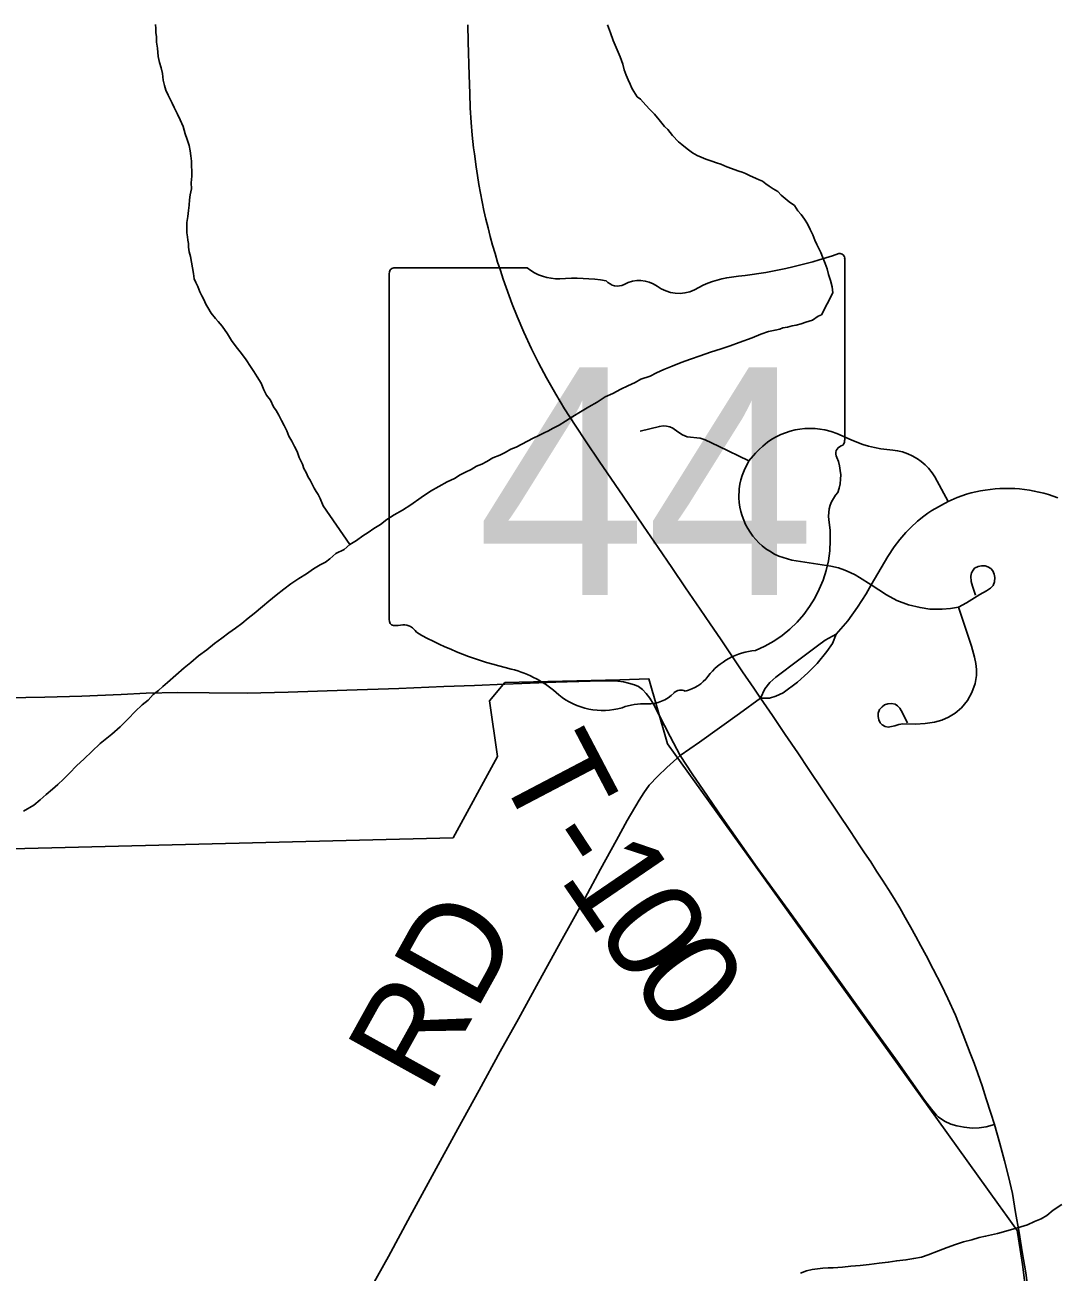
# Model space of a CAD drawing. Extents: x 103424 to 286016, y 38711 to 110967.
# Drawn here: x 143819 to 146990, y 92537 to 96372 of the extents above; entities that cross this region are included whole.
import ezdxf

# ---------------------------------------------------------------- set-up
doc = ezdxf.new("R2010")
doc.units = 0
for name, color, linetype in [('GM_X_City_Street', 7, 'Continuous'), ('GM_X_Corporation', 7, 'Continuous'), ('GM_X_County_Road', 7, 'Continuous'), ('GM_X_County_Road_Text', 7, 'Continuous'), ('GM_X_Major_River', 7, 'Continuous'), ('GM_X_Minor_River', 7, 'Continuous'), ('GM_X_State_Location', 7, 'Continuous'), ('GM_X_State_Route', 7, 'Continuous'), ('GM_X_State_Shield', 7, 'Continuous'), ('GM_X_Township_Road', 7, 'Continuous'), ('GM_X_Township_Road_Text', 7, 'Continuous')]:
    doc.layers.add(name, color=color, linetype=linetype)

msp = doc.modelspace()

# ---------------------------------------------------------------- linework, layer by layer
at = {"layer": 'GM_X_City_Street'}
for points in [[(145711.3, 95122.9), (145770.3, 95137.1), (145781.9, 95139.3), (145791.8, 95138.4), (145802.1, 95135.9), (145812, 95132), (145827.1, 95120.1), (145840.8, 95110.9), (145855.8, 95105.7), (145895.8, 95101.1), (145911.3, 95095.9), (145952.1, 95077), (146045.3, 95031.3)], [(146422, 94649.8), (146386.2, 94672.7), (146371.9, 94680.8), (146357, 94688.2), (146340.6, 94695.2), (146321.2, 94702.1), (146297.1, 94707.8), (146270.8, 94711.9), (146177.8, 94726.4), (146164, 94729.6), (146150.6, 94733.7), (146137.5, 94738.7), (146124.7, 94744.7), (146109.6, 94753.3), (146097.8, 94761.2), (146086.7, 94769.9), (146076.4, 94779.3), (146066.6, 94789.4), (146057.5, 94800.2), (146049.2, 94811.6), (146041.9, 94823.5), (146035.1, 94835.9), (146029.6, 94848.7), (146024.8, 94861.9), (146020.8, 94875.5), (146018.1, 94889.2), (146016, 94903.2), (146015, 94917.1), (146016, 94945.3), (146018.1, 94959.2), (146020.9, 94972.9), (146024.9, 94986.4), (146030.7, 95002), (146045.3, 95031.3), (146066.3, 95055), (146076.9, 95066.4), (146087.9, 95076.9), (146103.1, 95088.9), (146115.9, 95097.6), (146129.5, 95105.3), (146143.3, 95112.1), (146157.7, 95117.9), (146172.3, 95122.7), (146187.4, 95126.4), (146202.5, 95129.1), (146217.9, 95130.7), (146233.5, 95131.2), (146248.9, 95130.7), (146264.2, 95129), (146279.6, 95126.4), (146298.2, 95121.5), (146316.3, 95115.1), (146360.3, 95095.6), (146378, 95088.4), (146395.8, 95082), (146413.9, 95076.6), (146432.3, 95072.2), (146451, 95068.7), (146469.8, 95066.2), (146488.5, 95064.6), (146503.1, 95062.4), (146517.6, 95058.8), (146534.5, 95053.1), (146548.1, 95046.9), (146563.7, 95037.9), (146575.8, 95029.2), (146587.4, 95019.6), (146597.7, 95008.9), (146609, 94995), (146617.3, 94982.5), (146658.1, 94906.7)], [(146314.1, 94498), (146349.5, 94539.4), (146379.2, 94581.5), (146406.1, 94622.2), (146422, 94649.8), (146472.7, 94737.7), (146492.4, 94767), (146510.1, 94789.4), (146528.7, 94811.4), (146543.4, 94826.2), (146563.8, 94845.8), (146583.5, 94861.6), (146595.6, 94870.4), (146608.1, 94878.8), (146658.1, 94906.7), (146686.1, 94918.8), (146700.2, 94923.9), (146714.6, 94928.5), (146729.2, 94932.6), (146744, 94936.2), (146757.6, 94939.1), (146772.5, 94941.6), (146787.6, 94943.7), (146802.7, 94945.3), (146817.8, 94946.3), (146832.9, 94946.8), (146863.1, 94946.1), (146877.9, 94945), (146893.1, 94943.5), (146908.2, 94941.3), (146923, 94938.6), (146937.6, 94935.5), (146952.5, 94931.7), (146966.8, 94927.6), (146981.1, 94922.9), (146995.5, 94917.6)], [(146422, 94649.8), (146468.8, 94619), (146500.8, 94602.2), (146536.8, 94588.4), (146571.9, 94580), (146601.7, 94575.4), (146639.8, 94575), (146665.3, 94577), (146689.9, 94581.3), (146714.5, 94594.6), (146755.7, 94620.7), (146776.1, 94631.9), (146788.5, 94639.7), (146796.7, 94647.9), (146801.4, 94659.7), (146802.3, 94672.2), (146800.3, 94682.9), (146795.7, 94693.1), (146789.6, 94700.8), (146780.3, 94705.9), (146772.1, 94708), (146761.3, 94708.5), (146750.3, 94706.1), (146739.8, 94701.3), (146734.9, 94695.6), (146730, 94686.5), (146728.5, 94677.1), (146729.3, 94660.1), (146733.3, 94645.6), (146742.5, 94618.2)], [(146533, 94225.7), (146514.1, 94263.1), (146509.3, 94270.6), (146502.7, 94277.8), (146495.7, 94282.6), (146484.5, 94284.7), (146473.1, 94284.2), (146463.1, 94281.2), (146455.1, 94274.9), (146447.5, 94266.2), (146443.3, 94254.9), (146442.9, 94245.1), (146444.7, 94234.5), (146449, 94225.7), (146455.6, 94219.7), (146464.3, 94214.8), (146474.1, 94212.5), (146494.2, 94216.2), (146506.5, 94220.6), (146518.6, 94222.6), (146557.6, 94222), (146587.9, 94223.3), (146616.5, 94227.3), (146639.4, 94233.6), (146659.5, 94242.8), (146680.1, 94255.4), (146699.6, 94272), (146718, 94294.4), (146731.7, 94319), (146741.4, 94346.5), (146745.5, 94371.2), (146746, 94389.5), (146743.7, 94408.4), (146739.2, 94427.4), (146730, 94461.2), (146689.9, 94581.3)], [(146081.5, 94301.5), (146108.9, 94302), (146128.6, 94307.2), (146151.4, 94318.1), (146194.9, 94351), (146226.7, 94379.3), (146255.7, 94408.1), (146285.3, 94445.5), (146302.7, 94470.1), (146314.1, 94498)], [(146081.5, 94301.5), (146094.9, 94330), (146109.9, 94350.1), (146128.6, 94365.7), (146199.6, 94419.4), (146256.3, 94462.6), (146280.4, 94480.4), (146314.1, 94498)]]:
    msp.add_lwpolyline(points, dxfattribs=at)
at = {"layer": 'GM_X_Corporation'}
msp.add_lwpolyline([(146895.4, 92495.6), (146886.6, 92560.4), (146871.8, 92658.5), (146870.8, 92664.2), (146839.9, 92707.3), (146813, 92744.7), (146625.6, 93005.7), (145897.3, 94018.9), (145818.6, 94128.6), (145795.2, 94161.1), (145791.2, 94175.2), (145738.1, 94360.5), (145648.8, 94358.3), (145295.1, 94349.3), (145247.5, 94293.3), (145272.1, 94121.7), (145135.5, 93872.2), (143199.9, 93823.5)], dxfattribs=at)
at = {"layer": 'GM_X_County_Road'}
for points in [[(145834.2, 94124.9), (145893.3, 94166), (146016.2, 94254.4), (146081.5, 94301.5)], [(144869.2, 92463.4), (144936.8, 92584.7), (145004, 92708.4), (145071.1, 92832.2), (145150.5, 92976.9), (145215.7, 93095.9), (145280.9, 93214.9), (145336.6, 93315.7), (145392.3, 93416.5), (145466.4, 93551.1), (145540.5, 93685.6), (145589.5, 93775.4), (145638.4, 93865.3), (145670.7, 93925.5), (145708.1, 93987.4), (145722.4, 94010.3), (145739.1, 94033.7), (145765.1, 94061.5), (145793.4, 94088.1), (145834.2, 94124.9)]]:
    msp.add_lwpolyline(points, dxfattribs=at)
at = {"layer": 'GM_X_Major_River'}
for points in [[(146082.1, 95420.7), (146106.1, 95429.2), (146126.2, 95433.6), (146140.3, 95435.8), (146150.3, 95440.1), (146164.4, 95442.3), (146178.5, 95446.6), (146190.5, 95448.9), (146206.6, 95453.2), (146220.6, 95457.5), (146240.7, 95463.9), (146258.6, 95476.4), (146268.7, 95480.6)], [(143846.1, 93972.3), (143865.9, 93988.9), (143883.8, 94005.3), (143903.7, 94021.9), (143919.6, 94036.3), (143937.4, 94052.8), (143955.3, 94071.3), (143977.1, 94093.9), (144000.9, 94114.5), (144024.7, 94137.2), (144050.5, 94161.9), (144086.3, 94190.8), (144112.1, 94213.5), (144135.9, 94238.2), (144157.7, 94260.8), (144179.5, 94281.4), (144197.4, 94295.8), (144213.3, 94312.3), (144229.2, 94324.7), (144243.1, 94337.1), (144257, 94349.4), (144308.6, 94394.8), (144328.5, 94411.3), (144352.4, 94432), (144378.3, 94450.6), (144402.1, 94469.2), (144424, 94485.8), (144445.9, 94502.3), (144465.9, 94516.8), (144485.8, 94531.3), (144505.7, 94547.9), (144523.6, 94562.3), (144549.4, 94583), (144569.3, 94599.5), (144591.2, 94618.1), (144615, 94636.7), (144636.9, 94653.3), (144660.9, 94669.9), (144684.8, 94684.4), (144706.7, 94699), (144726.7, 94711.4), (144742.7, 94719.8), (144756.6, 94730.2), (144774.5, 94746.7), (144800.5, 94759.2), (144818.4, 94773.7), (144838.4, 94786.2), (144858.3, 94800.7), (144874.2, 94811.1), (144892.2, 94823.5), (144912.1, 94836), (144932, 94850.5), (144954, 94865), (144980, 94879.6), (145005.9, 94896.3), (145037.8, 94919.1), (145065.7, 94937.7), (145091.6, 94952.4), (145117.6, 94967), (145139.6, 94977.5), (145157.6, 94987.9), (145173.6, 94996.3), (145191.6, 95004.7), (145207.6, 95015), (145223.6, 95021.4), (145239.6, 95029.8), (145257.5, 95040.2), (145279.6, 95048.7), (145295.6, 95057), (145313.6, 95067.5), (145329.6, 95073.8), (145381.6, 95101), (145399.6, 95109.4), (145415.6, 95117.8), (145429.6, 95124.1), (145441.6, 95130.4), (145461.6, 95140.8), (145481.5, 95153.3), (145503.5, 95167.8), (145527.4, 95182.4), (145553.4, 95197), (145579.3, 95211.6), (145603.3, 95228.2), (145627.3, 95238.8), (145651.3, 95251.3), (145673.3, 95261.8), (145695.3, 95272.3), (145713.3, 95282.7), (145741.4, 95291.3), (145761.3, 95301.8), (145783.4, 95312.3), (145809.4, 95322.8), (145837.5, 95333.4), (145865.5, 95344), (145895.6, 95354.7), (145927.7, 95365.4), (145959.8, 95376), (145987.9, 95384.6), (146015.9, 95395.2), (146056, 95410.1), (146082.1, 95420.7)], [(143814.1, 93953.6), (143846.1, 93972.3)]]:
    msp.add_lwpolyline(points, dxfattribs=at)
at = {"layer": 'GM_X_Minor_River'}
for points in [[(144818.4, 94773.7), (144735.5, 94893.4), (144727.1, 94915.5), (144720.8, 94927.5), (144714.6, 94937.5), (144708.3, 94947.5), (144702.1, 94959.5), (144695.8, 94971.5), (144689.6, 94981.5), (144683.3, 94995.5), (144677, 95007.5), (144672.7, 95021.6), (144662.3, 95041.6), (144655.9, 95059.7), (144647.5, 95075.7), (144639.2, 95091.7), (144630.8, 95107.7), (144624.5, 95123.8), (144616.1, 95139.8), (144607.7, 95155.8), (144599.4, 95171.8), (144591.1, 95185.8), (144582.8, 95197.8), (144574.3, 95217.9), (144562, 95233.8), (144553.6, 95249.8), (144545.2, 95269.9), (144532.7, 95289.8), (144522.3, 95305.8), (144512, 95321.8), (144499.5, 95341.8), (144485, 95361.7), (144468.5, 95381.6), (144454, 95401.6), (144441.6, 95421.5), (144425, 95445.5), (144412.6, 95459.4), (144404.4, 95469.4), (144392, 95485.3), (144381.6, 95503.3), (144375.3, 95513.3), (144369, 95527.3), (144362.8, 95539.3), (144356.5, 95551.4), (144350.1, 95567.4), (144343.9, 95579.4), (144339.6, 95591.5), (144337.3, 95607.6), (144328.3, 95659.9), (144324, 95674), (144321.8, 95688.1), (144321.5, 95700.2), (144319.3, 95710.3), (144319.2, 95720.4), (144316.9, 95732.5), (144316.6, 95752.7), (144316.3, 95764.8), (144320.1, 95783), (144321.7, 95801.3), (144323.5, 95817.5), (144325.2, 95833.6), (144326.9, 95849.8), (144330.6, 95868.1), (144330.3, 95886.3), (144332, 95906.5), (144331.7, 95922.7), (144331.4, 95938.8), (144331.1, 95953), (144328.8, 95969.1), (144326.5, 95985.2), (144324.2, 96001.3), (144317.8, 96019.4), (144311.4, 96037.5), (144305, 96059.6), (144296.6, 96079.6), (144288.2, 96097.6), (144277.7, 96117.7), (144271.4, 96131.7), (144265.2, 96143.7), (144258.9, 96155.7), (144252.5, 96171.8), (144248.2, 96185.8), (144243.9, 96201.9), (144241.5, 96222.1), (144237.2, 96240.2), (144232.9, 96256.3), (144228.5, 96274.4), (144226, 96300.6), (144223.7, 96318.7), (144223.4, 96334.9), (144221.1, 96349), (144220.9, 96361.1), (144220.7, 96373.2)], [(146268.7, 95480.6), (146303.8, 95547.9), (146301.4, 95566), (146297, 95586.1), (146290.6, 95604.2), (146286.3, 95622.3), (146280, 95638.4), (146271.5, 95658.4), (146267.2, 95672.5), (146261, 95684.5), (146254.7, 95696.5), (146248.4, 95710.5), (146242, 95726.6), (146233.7, 95742.6), (146225.3, 95760.6), (146217, 95774.6), (146206.6, 95788.6), (146196.3, 95800.5), (146185.9, 95816.5), (146169.6, 95828.3), (146157.3, 95838.2), (146145, 95848.1), (146134.7, 95860), (146120.5, 95867.8), (146108.2, 95875.7), (146098, 95883.6), (146087.8, 95891.5), (146077.6, 95895.4), (146067.4, 95899.2), (146047.1, 95909), (146034.9, 95914.8), (146024.7, 95918.7), (146014.5, 95922.5), (145978, 95936), (145959.7, 95943.8), (145945.5, 95947.5), (145931.3, 95953.4), (145913, 95959.1), (145898.8, 95964.9), (145886.6, 95970.7), (145872.3, 95978.6), (145855.9, 95990.4), (145839.5, 96004.2), (145829.3, 96012.1), (145810.8, 96032), (145796.4, 96049.9), (145786.1, 96059.9), (145777.8, 96069.8), (145769.6, 96079.8), (145755.1, 96097.7), (145740.8, 96111.6), (145728.4, 96125.5), (145712, 96143.4), (145701.7, 96151.3), (145691.3, 96167.2), (145685.1, 96177.2), (145680.8, 96189.3), (145674.5, 96203.3), (145668.2, 96217.3), (145661.9, 96233.4), (145657.5, 96251.5), (145649.1, 96273.6), (145640.6, 96295.6), (145628, 96323.7), (145619.5, 96347.8), (145611, 96371.9)], [(146204.5, 92533.7), (146222.6, 92540.1), (146240.6, 92544.5), (146256.7, 92546.8), (146272.8, 92549.1), (146289, 92549.4), (146305.1, 92549.7), (146333.3, 92552.2), (146359.5, 92554.7), (146387.7, 92557.2), (146415.9, 92559.7), (146446.1, 92564.3), (146474.3, 92566.9), (146500.4, 92571.4), (146528.7, 92573.9), (146552.8, 92578.4), (146576.9, 92582.8), (146597, 92589.3), (146629, 92602), (146655.1, 92612.5), (146681.2, 92621.1), (146705.2, 92629.6), (146731.3, 92636.1), (146753.4, 92642.6), (146773.5, 92647), (146791.6, 92651.3), (146809.7, 92655.7), (146871.9, 92673), (146902, 92681.6), (146924, 92692.1), (146944.1, 92700.5), (146962.1, 92711), (146981.9, 92727.5), (147007.9, 92744.1)]]:
    msp.add_lwpolyline(points, dxfattribs=at)
at = {"layer": 'GM_X_State_Route'}
for points in [[(146876.6, 92657.8), (146866, 92719.7), (146856, 92778), (146843.6, 92831), (146831.8, 92878.7), (146817.7, 92931.7), (146801.1, 92990.3), (146790, 93025.2), (146775.8, 93069.5), (146763.5, 93109.6), (146749.4, 93147.3), (146738.2, 93179.1), (146726.4, 93210.3), (146705.1, 93266.6), (146680.9, 93326.2), (146657.3, 93377.9), (146637.6, 93418.5), (146612.7, 93467.7), (146590.4, 93509.9), (146574.8, 93539.6), (146559, 93569.1), (146542.9, 93598.3), (146526.3, 93627.4), (146509.4, 93656.3), (146492.1, 93685), (146474.7, 93713.5), (146456.9, 93741.8), (146438.5, 93770), (146420.1, 93798.1), (146401.5, 93826), (146384.8, 93851), (146357.9, 93891.1), (146319.6, 93948.3), (146271.8, 94019.7), (146229.9, 94082.4), (146195.6, 94133.6), (146157.4, 94189.8), (146117.9, 94247.9), (146081.5, 94301.5), (146060.3, 94332.7), (146026.1, 94383), (145992.8, 94432), (145957.7, 94483.7), (145926.1, 94530.1), (145895.7, 94574.9), (145850.6, 94641.3), (145808.3, 94703.5), (145766.9, 94764.5), (145721.8, 94830.8), (145659.1, 94923.1), (145585.4, 95030.8), (145544.6, 95089.8), (145511.3, 95140.6), (145478.6, 95191.4), (145451.2, 95236.9), (145422.5, 95286.5), (145398, 95332.6), (145377, 95375.8), (145353.7, 95426.6), (145333.2, 95475.1), (145317.7, 95513.3), (145308.1, 95538.9), (145298.5, 95564.6), (145289.5, 95590.4), (145281, 95616.4), (145272.7, 95642.5), (145264.6, 95668.7), (145257.1, 95695), (145250, 95721.4), (145243.3, 95747.9), (145236.7, 95774.5), (145230.7, 95801.2), (145225.2, 95828), (145219.7, 95854.8), (145214.9, 95881.7), (145210.4, 95908.7), (145206.4, 95935.8), (145201.1, 95975.7), (145198.8, 95993.6), (145194.6, 96032.6), (145191.3, 96071.8), (145188.3, 96116.5), (145186.8, 96160.9), (145184.8, 96217.5), (145182, 96320.2), (145180.9, 96372.1)], [(146936, 92254.1), (146928.4, 92308.8), (146919.7, 92370.5), (146907.7, 92456.6), (146897, 92533.8), (146886.3, 92598.9), (146876.6, 92657.8)]]:
    msp.add_lwpolyline(points, dxfattribs=at)
at = {"layer": 'GM_X_State_Shield'}
for p, q in [((146340.2, 95095), (146340.2, 95651.2)), ((145363.4, 95624.8), (144953.1, 95624.8)), ((144939.3, 95606.5), (144939.3, 94543.3)), ((146340, 95095.1), (146340.2, 95095))]:
    msp.add_line(p, q, dxfattribs=at)
for centre, radius, start, end in [((145841.2, 97074.4), 1485.6, 275.8445, 288.9065), ((146324.6, 95653.5), 15.6, 351.8621, 97.738), ((144955.4, 95608.8), 16.2, 98.1301, 188.1301), ((145461.1, 95748.2), 157.4, 231.6195, 271.1119), ((145513.2, 95027.9), 565.1, 80.4867, 94.9883), ((145641.5, 95614.3), 45.4, 219.7921, 297.1024), ((145708.2, 95491.4), 94.4, 54.4667, 119.1411), ((146030.7, 95300.1), 298.9, 97.3462, 120.7689), ((145830.1, 95660), 113.6, 233.8562, 294.8282), ((146336.6, 95054.1), 24.1, 107.944, 210.337), ((146323.5, 95092.8), 16.7, 289.6038, 7.7341), ((146183, 94983.8), 144.9, 340.033, 23.6496), ((146396, 94862.2), 105.4, 136.8065, 186.9296), ((145924.4, 94791.5), 371.6, 292.3089, 8.9858), ((144955.5, 94541), 16.4, 171.9584, 258.3066), ((144958, 94649.7), 124.9, 267.339, 280.6039), ((144983.6, 94481.9), 45.1, 29.7484, 93.2717), ((145552.4, 95437.2), 1072.8, 240.4129, 257.1985), ((146081.1, 94244.8), 203.5, 94.4031, 142.5768), ((145232.5, 94065.6), 335.7, 47.1842, 75.836), ((145823.2, 94440.2), 120, 282.8732, 323.2771), ((145595.6, 94476.7), 213, 230.7004, 286.2918), ((145734.2, 94397.1), 113.5, 268.777, 315.5493), ((145836.8, 94294.1), 32, 65.7517, 132.6484), ((145718.6, 94109.1), 175, 85.6951, 111.2099)]:
    msp.add_arc(centre, radius, start, end, dxfattribs=at)
at = {"layer": 'GM_X_Township_Road'}
for points in [[(145295, 94344.2), (145452.1, 94350.5), (145592.7, 94355.2), (145642, 94354.3), (145659.7, 94351.7), (145675.1, 94348.1), (145693.3, 94342.8), (145705.8, 94337), (145718.2, 94328.6), (145729.7, 94316.2), (145740.5, 94301.8), (145751.8, 94283.5), (145803.4, 94184.1), (145834.2, 94124.9)], [(142937.2, 94278.7), (143035.5, 94279.6), (143141.8, 94281.8), (143257.9, 94284.9), (143409, 94291.2), (143501.3, 94295.1), (143593.5, 94298.9), (143678.2, 94300.6), (143762.9, 94302.2), (143880.3, 94304.4), (143994.1, 94307.9), (144114.2, 94313.2), (144191.7, 94317.2), (144289.1, 94319), (144385.3, 94317.7), (144501.8, 94317.2), (144628.4, 94320.3), (144718.6, 94323.3), (144808.9, 94326.3), (144968.7, 94331.4), (145107.3, 94337.6), (145201.2, 94340.9), (145295, 94344.2)], [(145834.2, 94124.9), (145871, 94069), (145917.7, 94000.6), (145964.4, 93932.2), (146017.9, 93856.7), (146071.3, 93781.2), (146168.1, 93647.6), (146265, 93513.9), (146361.3, 93379.9), (146428.8, 93286), (146496.3, 93192.2), (146586.1, 93065), (146606.8, 93037.5), (146622.5, 93019.5)], [(146622.5, 93019.5), (146628.1, 93013.7), (146647.5, 93000.6), (146666.9, 92991.8), (146685.2, 92986.5), (146707.5, 92981.8), (146732.3, 92979.4), (146753.6, 92980.3), (146775.3, 92983.4), (146801.1, 92990.3)]]:
    msp.add_lwpolyline(points, dxfattribs=at)

# ---------------------------------------------------------------- texts
at = {"layer": 'GM_X_County_Road_Text'}
msp.add_text('RD', height=301.87, rotation=60.9941, dxfattribs=at).set_placement((145063.1, 93078.8))
at = {"layer": 'GM_X_State_Location'}
for s, p in [('s', (145624, 95004.2)), ('r', (145623.9, 95004.2))]:
    msp.add_text(s, height=1.01, dxfattribs=at).set_placement(p)
msp.add_text('44', height=1.01, rotation=0, dxfattribs=at).set_placement((145370.6, 94931))
at = {"layer": 'GM_X_State_Shield'}
msp.add_text('44', height=700.44, dxfattribs=at).set_placement((145208.1, 94618.3))
at = {"layer": 'GM_X_Township_Road_Text'}
for s, rotation, p in [('T', 297.6767, (145266.6, 94085.7)), ('-', 303.2998, (145387.8, 93857.9)), ('1', 304.3258, (145459.2, 93749.4)), ('0', 305.3884, (145567.5, 93590.8)), ('0', 305.6826, (145676.2, 93437.9))]:
    msp.add_text(s, height=301.9, rotation=rotation, dxfattribs=at).set_placement(p)

doc.saveas('drawing.dxf')
